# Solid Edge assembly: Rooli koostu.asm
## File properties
Author: Türk
Template: Iso Assembly.asm
Last saved by: Türk
Revision: 2
Application: Solid Edge
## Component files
Rool.par
Rooli ilu.par
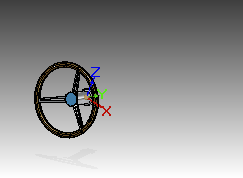
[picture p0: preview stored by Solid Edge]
